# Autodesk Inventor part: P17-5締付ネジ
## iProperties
Created: 2008-07
Part Number: P17-5締付ネジ
Document SubType Name: Modeling
Designer: y-shimohigashi
Density: 1 g/cm^3
Stock Number: P17-5締付ネジ
Author: y-shimohigashi
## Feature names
1. 押し出し1 [Extrusion]
2. 押し出し2 [Extrusion]
3. 穴1 [Hole]
4. 穴2 [Hole]
